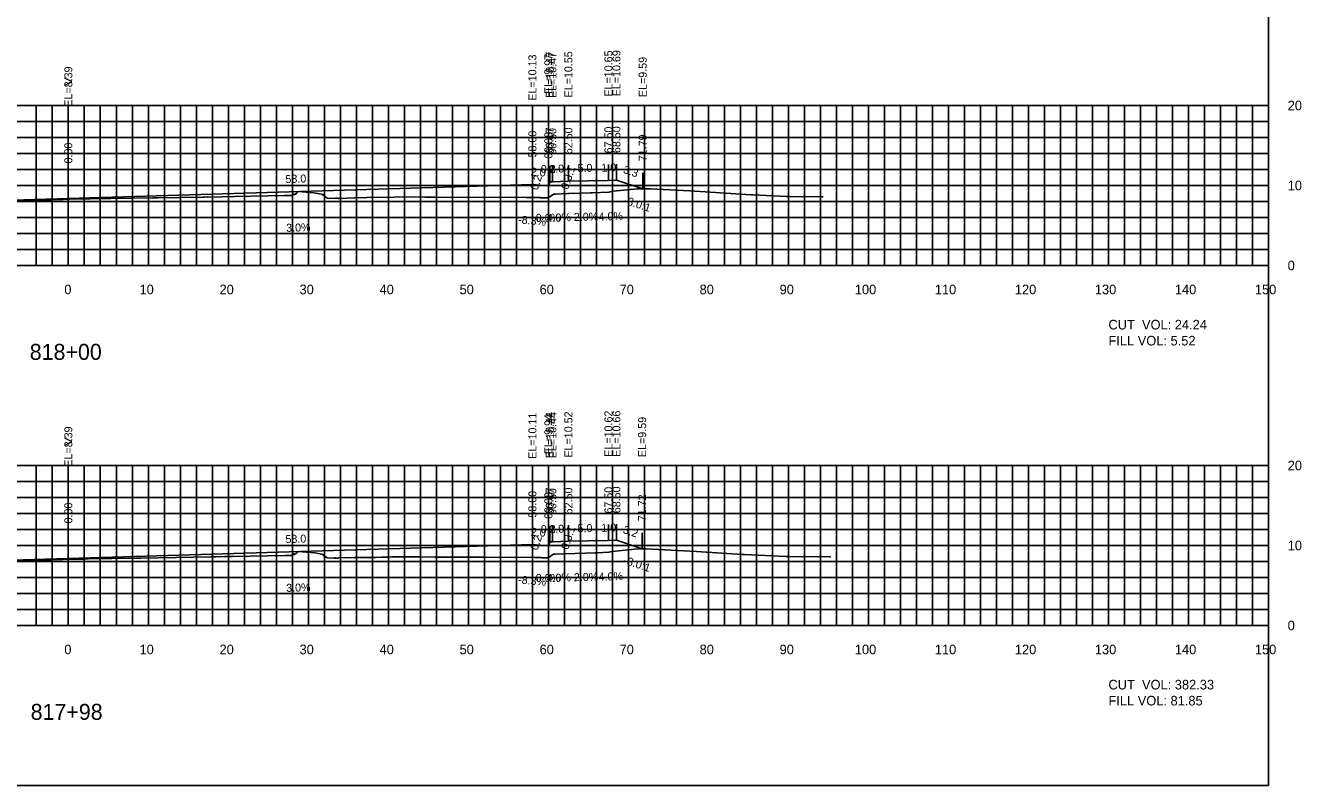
# Model space of a CAD drawing. Extents: x 1797419 to 1809236, y 248759 to 251512.
# Drawn here: x 1805685.6 to 1805845.1, y 250417.3 to 250512.3 of the extents above; entities that cross this region are included whole.
import ezdxf

# ---------------------------------------------------------------- set-up
doc = ezdxf.new("R2010")
doc.units = 0
for name, color, linetype in [('1', 7, 'Continuous'), ('10', 7, 'Continuous'), ('3', 7, 'Continuous'), ('31', 7, 'Continuous'), ('4', 7, 'Continuous'), ('60', 7, 'Continuous'), ('ANNO-TXT', 7, 'Continuous'), ('CL-CNST', 7, 'Continuous'), ('Level 62', 7, 'Continuous'), ('M-ROADS', 7, 'Continuous')]:
    doc.layers.add(name, color=color, linetype=linetype)

msp = doc.modelspace()

# ---------------------------------------------------------------- linework, layer by layer
for p, q in [((1805749, 250492.39), (1805749, 250494.39)), ((1805751, 250492.22), (1805751, 250494.22)), ((1805751.17, 250492.72), (1805751.17, 250494.72)), ((1805751.5, 250492.72), (1805751.5, 250494.72)), ((1805753.5, 250492.8), (1805753.5, 250494.8)), ((1805758.5, 250492.9), (1805758.5, 250494.9)), ((1805759.5, 250492.94), (1805759.5, 250494.94)), ((1805691, 250490.65), (1805691, 250492.65)), ((1805762.79, 250491.85), (1805762.79, 250493.85)), ((1805749, 250447.37), (1805749, 250449.37)), ((1805751.17, 250447.7), (1805751.17, 250449.7)), ((1805751.5, 250447.7), (1805751.5, 250449.7)), ((1805753.5, 250447.78), (1805753.5, 250449.78)), ((1805758.5, 250447.88), (1805758.5, 250449.88)), ((1805759.5, 250447.92), (1805759.5, 250449.92)), ((1805751, 250447.2), (1805751, 250449.2)), ((1805762.72, 250446.85), (1805762.72, 250448.85)), ((1805691, 250445.65), (1805691, 250447.65))]:
    msp.add_line(p, q)
msp.add_lwpolyline([(1805541, 250417.26), (1805841, 250417.26), (1805841, 250607.26), (1805541, 250607.26)], close=True)
at = {"layer": '60'}
for p, q in [((1805841, 250482.26), (1805841, 250502.26)), ((1805841.06, 250502.26), (1805841, 250502.26)), ((1805841.06, 250492.26), (1805841, 250492.26)), ((1805541, 250482.26), (1805841, 250482.26)), ((1805691, 250482.2), (1805691, 250482.26)), ((1805701, 250482.2), (1805701, 250482.26)), ((1805711, 250482.2), (1805711, 250482.26)), ((1805721, 250482.2), (1805721, 250482.26)), ((1805731, 250482.2), (1805731, 250482.26)), ((1805741, 250482.2), (1805741, 250482.26)), ((1805751, 250482.2), (1805751, 250482.26)), ((1805761, 250482.2), (1805761, 250482.26)), ((1805771, 250482.2), (1805771, 250482.26)), ((1805781, 250482.2), (1805781, 250482.26)), ((1805791, 250482.2), (1805791, 250482.26)), ((1805801, 250482.2), (1805801, 250482.26)), ((1805811, 250482.2), (1805811, 250482.26)), ((1805821, 250482.2), (1805821, 250482.26)), ((1805831, 250482.2), (1805831, 250482.26)), ((1805841, 250482.2), (1805841, 250482.26)), ((1805841.06, 250482.26), (1805841, 250482.26)), ((1805841, 250437.26), (1805841, 250457.26)), ((1805841.06, 250457.26), (1805841, 250457.26)), ((1805841.06, 250447.26), (1805841, 250447.26)), ((1805541, 250437.26), (1805841, 250437.26)), ((1805691, 250437.2), (1805691, 250437.26)), ((1805701, 250437.2), (1805701, 250437.26)), ((1805711, 250437.2), (1805711, 250437.26)), ((1805721, 250437.2), (1805721, 250437.26)), ((1805731, 250437.2), (1805731, 250437.26)), ((1805741, 250437.2), (1805741, 250437.26)), ((1805751, 250437.2), (1805751, 250437.26)), ((1805761, 250437.2), (1805761, 250437.26)), ((1805771, 250437.2), (1805771, 250437.26)), ((1805781, 250437.2), (1805781, 250437.26)), ((1805791, 250437.2), (1805791, 250437.26)), ((1805801, 250437.2), (1805801, 250437.26)), ((1805811, 250437.2), (1805811, 250437.26)), ((1805821, 250437.2), (1805821, 250437.26)), ((1805831, 250437.2), (1805831, 250437.26)), ((1805841, 250437.2), (1805841, 250437.26)), ((1805841.06, 250437.26), (1805841, 250437.26))]:
    msp.add_line(p, q, dxfattribs=at)
at = {"layer": 'CL-CNST'}
for points in [[(1805579.09, 250495.21), (1805598.5, 250488.74), (1805599.5, 250488.7), (1805604.5, 250488.6), (1805606.5, 250488.52), (1805606.83, 250488.52), (1805607, 250488.02), (1805609, 250488.19), (1805691, 250490.65), (1805749, 250492.39), (1805751, 250492.22), (1805751.17, 250492.72), (1805751.5, 250492.72), (1805753.5, 250492.8), (1805758.5, 250492.9), (1805759.5, 250492.94), (1805762.79, 250491.85)], [(1805579.4, 250450.14), (1805598.5, 250443.78), (1805599.5, 250443.74), (1805604.5, 250443.64), (1805606.5, 250443.56), (1805606.83, 250443.56), (1805607, 250443.06), (1805609, 250443.22), (1805691, 250445.65), (1805749, 250447.37), (1805751, 250447.2), (1805751.17, 250447.7), (1805751.5, 250447.7), (1805753.5, 250447.78), (1805758.5, 250447.88), (1805759.5, 250447.92), (1805762.72, 250446.85)]]:
    msp.add_lwpolyline(points, dxfattribs=at)
at = {"layer": 'Level 62'}
for p, q in [((1805541, 250502.26), (1805841, 250502.26)), ((1805687, 250482.26), (1805687, 250502.26)), ((1805689, 250482.26), (1805689, 250502.26)), ((1805691, 250482.26), (1805691, 250502.26)), ((1805693, 250482.26), (1805693, 250502.26)), ((1805695, 250482.26), (1805695, 250502.26)), ((1805697, 250482.26), (1805697, 250502.26)), ((1805699, 250482.26), (1805699, 250502.26)), ((1805701, 250482.26), (1805701, 250502.26)), ((1805703, 250482.26), (1805703, 250502.26)), ((1805705, 250482.26), (1805705, 250502.26)), ((1805707, 250482.26), (1805707, 250502.26)), ((1805709, 250482.26), (1805709, 250502.26)), ((1805711, 250482.26), (1805711, 250502.26)), ((1805713, 250482.26), (1805713, 250502.26)), ((1805715, 250482.26), (1805715, 250502.26)), ((1805717, 250482.26), (1805717, 250502.26)), ((1805719, 250482.26), (1805719, 250502.26)), ((1805721, 250482.26), (1805721, 250502.26)), ((1805723, 250482.26), (1805723, 250502.26)), ((1805725, 250482.26), (1805725, 250502.26)), ((1805727, 250482.26), (1805727, 250502.26)), ((1805729, 250482.26), (1805729, 250502.26)), ((1805731, 250482.26), (1805731, 250502.26)), ((1805733, 250482.26), (1805733, 250502.26)), ((1805735, 250482.26), (1805735, 250502.26)), ((1805737, 250482.26), (1805737, 250502.26)), ((1805739, 250482.26), (1805739, 250502.26)), ((1805741, 250482.26), (1805741, 250502.26)), ((1805743, 250482.26), (1805743, 250502.26)), ((1805745, 250482.26), (1805745, 250502.26)), ((1805747, 250482.26), (1805747, 250502.26)), ((1805749, 250482.26), (1805749, 250502.26)), ((1805751, 250482.26), (1805751, 250502.26)), ((1805753, 250482.26), (1805753, 250502.26)), ((1805755, 250482.26), (1805755, 250502.26)), ((1805757, 250482.26), (1805757, 250502.26)), ((1805759, 250482.26), (1805759, 250502.26)), ((1805761, 250482.26), (1805761, 250502.26)), ((1805763, 250482.26), (1805763, 250502.26)), ((1805765, 250482.26), (1805765, 250502.26)), ((1805767, 250482.26), (1805767, 250502.26)), ((1805769, 250482.26), (1805769, 250502.26)), ((1805771, 250482.26), (1805771, 250502.26)), ((1805773, 250482.26), (1805773, 250502.26)), ((1805775, 250482.26), (1805775, 250502.26)), ((1805777, 250482.26), (1805777, 250502.26)), ((1805779, 250482.26), (1805779, 250502.26)), ((1805781, 250482.26), (1805781, 250502.26)), ((1805783, 250482.26), (1805783, 250502.26)), ((1805785, 250482.26), (1805785, 250502.26)), ((1805787, 250482.26), (1805787, 250502.26)), ((1805789, 250482.26), (1805789, 250502.26)), ((1805791, 250482.26), (1805791, 250502.26)), ((1805793, 250482.26), (1805793, 250502.26)), ((1805795, 250482.26), (1805795, 250502.26)), ((1805797, 250482.26), (1805797, 250502.26)), ((1805799, 250482.26), (1805799, 250502.26)), ((1805801, 250482.26), (1805801, 250502.26)), ((1805803, 250482.26), (1805803, 250502.26)), ((1805805, 250482.26), (1805805, 250502.26)), ((1805807, 250482.26), (1805807, 250502.26)), ((1805809, 250482.26), (1805809, 250502.26)), ((1805811, 250482.26), (1805811, 250502.26)), ((1805813, 250482.26), (1805813, 250502.26)), ((1805815, 250482.26), (1805815, 250502.26)), ((1805817, 250482.26), (1805817, 250502.26)), ((1805819, 250482.26), (1805819, 250502.26)), ((1805821, 250482.26), (1805821, 250502.26)), ((1805823, 250482.26), (1805823, 250502.26)), ((1805825, 250482.26), (1805825, 250502.26)), ((1805827, 250482.26), (1805827, 250502.26)), ((1805829, 250482.26), (1805829, 250502.26)), ((1805831, 250482.26), (1805831, 250502.26)), ((1805833, 250482.26), (1805833, 250502.26)), ((1805835, 250482.26), (1805835, 250502.26)), ((1805837, 250482.26), (1805837, 250502.26)), ((1805839, 250482.26), (1805839, 250502.26)), ((1805841, 250482.26), (1805841, 250502.26)), ((1805541, 250500.26), (1805841, 250500.26)), ((1805541, 250498.26), (1805841, 250498.26)), ((1805541, 250496.26), (1805841, 250496.26)), ((1805541, 250494.26), (1805841, 250494.26)), ((1805541, 250492.26), (1805841, 250492.26)), ((1805541, 250490.26), (1805841, 250490.26)), ((1805541, 250488.26), (1805841, 250488.26)), ((1805541, 250486.26), (1805841, 250486.26)), ((1805541, 250484.26), (1805841, 250484.26)), ((1805541, 250482.26), (1805841, 250482.26)), ((1805541, 250457.26), (1805841, 250457.26)), ((1805687, 250437.26), (1805687, 250457.26)), ((1805689, 250437.26), (1805689, 250457.26)), ((1805691, 250437.26), (1805691, 250457.26)), ((1805693, 250437.26), (1805693, 250457.26)), ((1805695, 250437.26), (1805695, 250457.26)), ((1805697, 250437.26), (1805697, 250457.26)), ((1805699, 250437.26), (1805699, 250457.26)), ((1805701, 250437.26), (1805701, 250457.26)), ((1805703, 250437.26), (1805703, 250457.26)), ((1805705, 250437.26), (1805705, 250457.26)), ((1805707, 250437.26), (1805707, 250457.26)), ((1805709, 250437.26), (1805709, 250457.26)), ((1805711, 250437.26), (1805711, 250457.26)), ((1805713, 250437.26), (1805713, 250457.26)), ((1805715, 250437.26), (1805715, 250457.26)), ((1805717, 250437.26), (1805717, 250457.26)), ((1805719, 250437.26), (1805719, 250457.26)), ((1805721, 250437.26), (1805721, 250457.26)), ((1805723, 250437.26), (1805723, 250457.26)), ((1805725, 250437.26), (1805725, 250457.26)), ((1805727, 250437.26), (1805727, 250457.26)), ((1805729, 250437.26), (1805729, 250457.26)), ((1805731, 250437.26), (1805731, 250457.26)), ((1805733, 250437.26), (1805733, 250457.26)), ((1805735, 250437.26), (1805735, 250457.26)), ((1805737, 250437.26), (1805737, 250457.26)), ((1805739, 250437.26), (1805739, 250457.26)), ((1805741, 250437.26), (1805741, 250457.26)), ((1805743, 250437.26), (1805743, 250457.26)), ((1805745, 250437.26), (1805745, 250457.26)), ((1805747, 250437.26), (1805747, 250457.26)), ((1805749, 250437.26), (1805749, 250457.26)), ((1805751, 250437.26), (1805751, 250457.26)), ((1805753, 250437.26), (1805753, 250457.26)), ((1805755, 250437.26), (1805755, 250457.26)), ((1805757, 250437.26), (1805757, 250457.26)), ((1805759, 250437.26), (1805759, 250457.26)), ((1805761, 250437.26), (1805761, 250457.26)), ((1805763, 250437.26), (1805763, 250457.26)), ((1805765, 250437.26), (1805765, 250457.26)), ((1805767, 250437.26), (1805767, 250457.26)), ((1805769, 250437.26), (1805769, 250457.26)), ((1805771, 250437.26), (1805771, 250457.26)), ((1805773, 250437.26), (1805773, 250457.26)), ((1805775, 250437.26), (1805775, 250457.26)), ((1805777, 250437.26), (1805777, 250457.26)), ((1805779, 250437.26), (1805779, 250457.26)), ((1805781, 250437.26), (1805781, 250457.26)), ((1805783, 250437.26), (1805783, 250457.26)), ((1805785, 250437.26), (1805785, 250457.26)), ((1805787, 250437.26), (1805787, 250457.26)), ((1805789, 250437.26), (1805789, 250457.26)), ((1805791, 250437.26), (1805791, 250457.26)), ((1805793, 250437.26), (1805793, 250457.26)), ((1805795, 250437.26), (1805795, 250457.26)), ((1805797, 250437.26), (1805797, 250457.26)), ((1805799, 250437.26), (1805799, 250457.26)), ((1805801, 250437.26), (1805801, 250457.26)), ((1805803, 250437.26), (1805803, 250457.26)), ((1805805, 250437.26), (1805805, 250457.26)), ((1805807, 250437.26), (1805807, 250457.26)), ((1805809, 250437.26), (1805809, 250457.26)), ((1805811, 250437.26), (1805811, 250457.26)), ((1805813, 250437.26), (1805813, 250457.26)), ((1805815, 250437.26), (1805815, 250457.26)), ((1805817, 250437.26), (1805817, 250457.26)), ((1805819, 250437.26), (1805819, 250457.26)), ((1805821, 250437.26), (1805821, 250457.26)), ((1805823, 250437.26), (1805823, 250457.26)), ((1805825, 250437.26), (1805825, 250457.26)), ((1805827, 250437.26), (1805827, 250457.26)), ((1805829, 250437.26), (1805829, 250457.26)), ((1805831, 250437.26), (1805831, 250457.26)), ((1805833, 250437.26), (1805833, 250457.26)), ((1805835, 250437.26), (1805835, 250457.26)), ((1805837, 250437.26), (1805837, 250457.26)), ((1805839, 250437.26), (1805839, 250457.26)), ((1805841, 250437.26), (1805841, 250457.26)), ((1805541, 250455.26), (1805841, 250455.26)), ((1805541, 250453.26), (1805841, 250453.26)), ((1805541, 250451.26), (1805841, 250451.26)), ((1805541, 250449.26), (1805841, 250449.26)), ((1805541, 250447.26), (1805841, 250447.26)), ((1805541, 250445.26), (1805841, 250445.26)), ((1805541, 250443.26), (1805841, 250443.26)), ((1805541, 250441.26), (1805841, 250441.26)), ((1805541, 250439.26), (1805841, 250439.26)), ((1805541, 250437.26), (1805841, 250437.26))]:
    msp.add_line(p, q, dxfattribs=at)
at = {"layer": 'M-ROADS'}
for points in [[(1805676.62, 250490.24), (1805688.95, 250490.48), (1805690.34, 250490.51), (1805691.16, 250490.53), (1805701.54, 250490.7), (1805701.91, 250490.7), (1805702.2, 250490.7), (1805707.79, 250490.81), (1805708, 250490.81), (1805708.3, 250490.82), (1805708.38, 250490.81), (1805710.24, 250490.85), (1805711.76, 250490.88), (1805718.02, 250491.01), (1805718.95, 250490.99), (1805719.14, 250491.18), (1805719.17, 250491.18), (1805719.18, 250491.18), (1805719.22, 250491.13), (1805719.27, 250491.14), (1805719.27, 250491.15), (1805719.27, 250491.14), (1805719.27, 250491.13), (1805719.27, 250491.13), (1805719.28, 250491.14), (1805719.28, 250491.13), (1805719.28, 250491.1), (1805719.28, 250491.09), (1805719.28, 250491.09), (1805719.28, 250491.09), (1805719.28, 250491.09), (1805719.28, 250491.09), (1805719.32, 250491.17), (1805719.33, 250491.19), (1805719.35, 250491.16), (1805719.36, 250491.14), (1805719.38, 250491.2), (1805719.39, 250491.22), (1805719.41, 250491.22), (1805719.41, 250491.23), (1805719.43, 250491.23), (1805719.44, 250491.23), (1805719.45, 250491.26), (1805719.46, 250491.25), (1805719.47, 250491.24), (1805719.48, 250491.22), (1805719.49, 250491.21), (1805719.5, 250491.22), (1805719.51, 250491.26), (1805719.51, 250491.29), (1805719.73, 250491.5), (1805721.7, 250491.32), (1805722.68, 250491.16), (1805723.15, 250490.84), (1805723.36, 250490.69), (1805724.3, 250490.65), (1805724.34, 250490.66), (1805724.36, 250490.67), (1805724.39, 250490.68), (1805724.41, 250490.68), (1805724.45, 250490.68), (1805724.48, 250490.68), (1805724.51, 250490.66), (1805724.54, 250490.65), (1805724.58, 250490.66), (1805724.63, 250490.68), (1805724.67, 250490.67), (1805724.75, 250490.65), (1805724.81, 250490.63), (1805726.81, 250490.7), (1805728.32, 250490.74), (1805735.09, 250490.82), (1805735.56, 250490.81), (1805736.26, 250490.81), (1805736.81, 250490.8), (1805748.23, 250490.76), (1805749.29, 250490.76), (1805749.31, 250490.76), (1805749.52, 250490.76), (1805749.59, 250490.75), (1805749.79, 250490.75), (1805749.93, 250490.74), (1805749.96, 250490.74), (1805750.05, 250490.73), (1805750.14, 250490.72), (1805750.19, 250490.71), (1805750.21, 250490.71), (1805750.27, 250490.71), (1805750.33, 250490.71), (1805750.34, 250490.71), (1805750.37, 250490.71), (1805750.41, 250490.71), (1805750.43, 250490.71), (1805750.44, 250490.71), (1805750.47, 250490.71), (1805750.5, 250490.71), (1805750.5, 250490.71), (1805750.52, 250490.71), (1805750.96, 250490.71), (1805751.04, 250490.77), (1805751.62, 250491.17), (1805751.91, 250491.19), (1805753.37, 250491.24), (1805753.61, 250491.24), (1805756.25, 250491.33), (1805756.52, 250491.33), (1805758.57, 250491.42), (1805759.1, 250491.54), (1805762.11, 250491.85), (1805763.04, 250491.85), (1805763.26, 250491.85), (1805763.35, 250491.85), (1805763.69, 250491.85), (1805763.76, 250491.85), (1805768.66, 250491.59), (1805776.33, 250491.08), (1805776.57, 250491.08), (1805780.77, 250490.9), (1805781.02, 250490.9), (1805781.13, 250490.9), (1805785.23, 250490.86), (1805785.24, 250490.86), (1805785.33, 250490.86)], [(1805684.25, 250445.38), (1805688.95, 250445.48), (1805691.62, 250445.53), (1805693.03, 250445.56), (1805693.5, 250445.57), (1805699.4, 250445.67), (1805699.61, 250445.67), (1805700.05, 250445.67), (1805708.8, 250445.84), (1805709.13, 250445.85), (1805709.3, 250445.85), (1805709.42, 250445.85), (1805710.56, 250445.87), (1805711.48, 250445.89), (1805718.1, 250446.02), (1805718.95, 250446), (1805719.15, 250446.2), (1805719.17, 250446.2), (1805719.19, 250446.2), (1805719.22, 250446.15), (1805719.25, 250446.15), (1805719.25, 250446.16), (1805719.25, 250446.15), (1805719.25, 250446.14), (1805719.25, 250446.14), (1805719.25, 250446.14), (1805719.25, 250446.14), (1805719.25, 250446.14), (1805719.28, 250446.11), (1805719.31, 250446.13), (1805719.32, 250446.14), (1805719.35, 250446.21), (1805719.37, 250446.23), (1805719.38, 250446.2), (1805719.39, 250446.19), (1805719.41, 250446.24), (1805719.42, 250446.26), (1805719.43, 250446.26), (1805719.44, 250446.26), (1805719.45, 250446.26), (1805719.46, 250446.26), (1805719.47, 250446.29), (1805719.48, 250446.28), (1805719.49, 250446.27), (1805719.5, 250446.26), (1805719.51, 250446.24), (1805719.52, 250446.26), (1805719.52, 250446.29), (1805719.53, 250446.32), (1805719.72, 250446.51), (1805721.79, 250446.32), (1805722.67, 250446.18), (1805723.17, 250445.85), (1805723.36, 250445.71), (1805724.21, 250445.67), (1805724.25, 250445.68), (1805724.27, 250445.68), (1805724.3, 250445.69), (1805724.31, 250445.7), (1805724.35, 250445.7), (1805724.38, 250445.7), (1805724.4, 250445.68), (1805724.43, 250445.67), (1805724.47, 250445.68), (1805724.51, 250445.7), (1805724.55, 250445.69), (1805724.62, 250445.67), (1805724.69, 250445.65), (1805724.71, 250445.66), (1805724.78, 250445.73), (1805724.81, 250445.72), (1805726.81, 250445.76), (1805729.11, 250445.77), (1805729.44, 250445.77), (1805730.18, 250445.78), (1805731.01, 250445.81), (1805731.44, 250445.82), (1805733.33, 250445.85), (1805733.46, 250445.84), (1805733.65, 250445.84), (1805734.57, 250445.83), (1805735.05, 250445.83), (1805736.81, 250445.81), (1805736.81, 250445.81), (1805743.16, 250445.78), (1805749.3, 250445.75), (1805749.47, 250445.75), (1805749.77, 250445.74), (1805749.92, 250445.74), (1805749.97, 250445.74), (1805750.11, 250445.74), (1805750.22, 250445.73), (1805750.24, 250445.73), (1805750.3, 250445.72), (1805750.37, 250445.72), (1805750.41, 250445.71), (1805750.42, 250445.71), (1805750.47, 250445.71), (1805750.5, 250445.71), (1805750.51, 250445.71), (1805750.54, 250445.71), (1805750.56, 250445.71), (1805750.58, 250445.71), (1805750.59, 250445.71), (1805750.61, 250445.71), (1805750.63, 250445.71), (1805750.63, 250445.71), (1805750.65, 250445.71), (1805750.96, 250445.71), (1805751.02, 250445.75), (1805751.62, 250446.17), (1805751.83, 250446.18), (1805752.88, 250446.21), (1805753.06, 250446.22), (1805756.85, 250446.34), (1805757.05, 250446.35), (1805758.57, 250446.41), (1805758.96, 250446.5), (1805762.19, 250446.83), (1805762.48, 250446.85), (1805762.63, 250446.85), (1805762.8, 250446.85), (1805763.18, 250446.83), (1805763.19, 250446.83), (1805769.5, 250446.51), (1805775.2, 250446.13), (1805775.51, 250446.12), (1805780.72, 250445.9), (1805780.95, 250445.9), (1805781.08, 250445.9), (1805786.15, 250445.85), (1805786.16, 250445.85), (1805786.28, 250445.86)]]:
    msp.add_lwpolyline(points, dxfattribs=at)

# ---------------------------------------------------------------- texts
for s, rotation, p in [('0.3:1', 71.5647, (1805753.46, 250491.68)), ('-3.0:1', 341.5651, (1805760.35, 250490.02)), ('0.3:1', 71.5647, (1805753.46, 250446.66)), ('-3.0:1', 341.5651, (1805760.32, 250445.01))]:
    msp.add_text(s, height=1, rotation=rotation).set_placement(p)
at = {"layer": '1'}
for s, p in [('818+00', (1805686.18, 250470.46)), ('817+98', (1805686.29, 250425.46))]:
    msp.add_text(s, height=2, dxfattribs=at).set_placement(p)
at = {"layer": '10'}
for s, p in [('0', (1805690.5, 250478.66)), ('10', (1805699.9, 250478.66)), ('20', (1805709.9, 250478.66)), ('30', (1805719.9, 250478.66)), ('40', (1805729.9, 250478.66)), ('50', (1805739.9, 250478.66)), ('60', (1805749.9, 250478.66)), ('70', (1805759.9, 250478.66)), ('80', (1805769.9, 250478.66)), ('90', (1805779.9, 250478.66)), ('100', (1805789.3, 250478.66)), ('110', (1805799.3, 250478.66)), ('120', (1805809.3, 250478.66)), ('130', (1805819.3, 250478.66)), ('140', (1805829.3, 250478.66)), ('150', (1805839.3, 250478.66)), ('0', (1805690.5, 250433.66)), ('10', (1805699.9, 250433.66)), ('20', (1805709.9, 250433.66)), ('30', (1805719.9, 250433.66)), ('40', (1805729.9, 250433.66)), ('50', (1805739.9, 250433.66)), ('60', (1805749.9, 250433.66)), ('70', (1805759.9, 250433.66)), ('80', (1805769.9, 250433.66)), ('90', (1805779.9, 250433.66)), ('100', (1805789.3, 250433.66)), ('110', (1805799.3, 250433.66)), ('120', (1805809.3, 250433.66)), ('130', (1805819.3, 250433.66)), ('140', (1805829.3, 250433.66)), ('150', (1805839.3, 250433.66))]:
    msp.add_text(s, height=1.2, dxfattribs=at).set_placement(p)
at = {"layer": '3'}
for s, p in [('EL=10.13', (1805749.5, 250502.86)), ('EL=9.97', (1805751.5, 250503.69)), ('EL=10.47', (1805751.67, 250503.19)), ('EL=10.47', (1805752, 250503.19)), ('EL=10.55', (1805754, 250503.27)), ('EL=10.65', (1805759, 250503.37)), ('EL=10.69', (1805760, 250503.41)), ('EL=8.39', (1805691.5, 250502.11)), ('EL=9.59', (1805763.29, 250503.31)), ('58.00', (1805749.5, 250495.76)), ('60.00', (1805751.5, 250495.59)), ('60.17', (1805751.67, 250496.17)), ('60.50', (1805752, 250496.09)), ('62.50', (1805754, 250496.17)), ('67.50', (1805759, 250496.27)), ('68.50', (1805760, 250496.31)), ('0.00', (1805691.5, 250495.01)), ('71.79', (1805763.29, 250495.29)), ('EL=10.11', (1805749.5, 250458.09)), ('EL=9.94', (1805751.5, 250458.66)), ('EL=10.44', (1805751.67, 250458.17)), ('EL=10.44', (1805752, 250458.17)), ('EL=10.52', (1805754, 250458.25)), ('EL=10.62', (1805759, 250458.35)), ('EL=10.66', (1805760, 250458.35)), ('EL=8.39', (1805691.5, 250457.11)), ('EL=9.59', (1805763.22, 250458.31)), ('60.17', (1805751.67, 250451.15)), ('60.50', (1805752, 250451.07)), ('62.50', (1805754, 250451.15)), ('67.50', (1805759, 250451.25)), ('68.50', (1805760, 250451.29)), ('0.00', (1805691.5, 250450.01)), ('58.00', (1805749.5, 250450.74)), ('60.00', (1805751.5, 250450.57)), ('71.72', (1805763.22, 250450.29))]:
    msp.add_text(s, height=1, rotation=90, dxfattribs=at).set_placement(p)
at = {"layer": '31'}
for s, p in [('20', (1805843.4, 250501.66)), ('10', (1805843.4, 250491.66)), ('0', (1805843.4, 250481.66)), ('20', (1805843.4, 250456.66)), ('10', (1805843.4, 250446.66)), ('0', (1805843.4, 250436.66))]:
    msp.add_text(s, height=1.2, dxfattribs=at).set_placement(p)
at = {"layer": '4'}
for s, rotation, p in [('2.0', 355.2364, (1805748.77, 250493.51)), ('2.0', 2.2906, (1805751.13, 250493.81)), ('5.0', 1.1458, (1805754.65, 250493.93)), ('1.0', 2.2906, (1805757.63, 250493.97)), ('3.3', 341.5651, (1805760.27, 250493.84)), ('58.0', 1.7199, (1805718.15, 250492.56)), ('0.2', 71.5647, (1805749.64, 250491.6)), ('-8.3%', 355.2364, (1805747.19, 250487.52)), ('4.0%', 2.2906, (1805750.79, 250487.69)), ('2.0%', 1.1458, (1805754.19, 250487.82)), ('4.0%', 2.2906, (1805757.29, 250487.85)), ('3.0%', 1.7199, (1805718.24, 250486.46)), ('2.0', 355.2364, (1805748.77, 250448.49)), ('2.0', 2.2906, (1805751.13, 250448.79)), ('5.0', 1.1458, (1805754.65, 250448.9)), ('1.0', 2.2906, (1805757.63, 250448.95)), ('3.2', 341.5651, (1805760.24, 250448.83)), ('58.0', 1.6955, (1805718.15, 250447.55)), ('0.2', 71.5647, (1805749.64, 250446.58)), ('-8.3%', 355.2364, (1805747.19, 250442.5)), ('4.0%', 2.2906, (1805750.79, 250442.67)), ('2.0%', 1.1458, (1805754.19, 250442.79)), ('4.0%', 2.2906, (1805757.29, 250442.83)), ('3.0%', 1.6955, (1805718.24, 250441.45))]:
    msp.add_text(s, height=1, rotation=rotation, dxfattribs=at).set_placement(p)
for s, p in [('0.3', (1805750.05, 250493.82)), ('0.0%', (1805749.42, 250487.72)), ('0.3', (1805750.05, 250448.8)), ('0.0%', (1805749.42, 250442.7))]:
    msp.add_text(s, height=1, dxfattribs=at).set_placement(p)
at = {"layer": '60'}
for p in [(1805690.39, 250504.51), (1805690.39, 250459.51)]:
    msp.add_text('>', height=1.5, dxfattribs=at).set_placement(p)
at = {"layer": 'ANNO-TXT'}
for s, p in [('CUT  VOL: 24.24', (1805821, 250474.26)), ('FILL VOL: 5.52', (1805821, 250472.26)), ('CUT  VOL: 382.33', (1805821, 250429.26)), ('FILL VOL: 81.85', (1805821, 250427.26))]:
    msp.add_text(s, height=1.2, dxfattribs=at).set_placement(p)

doc.saveas('drawing.dxf')
